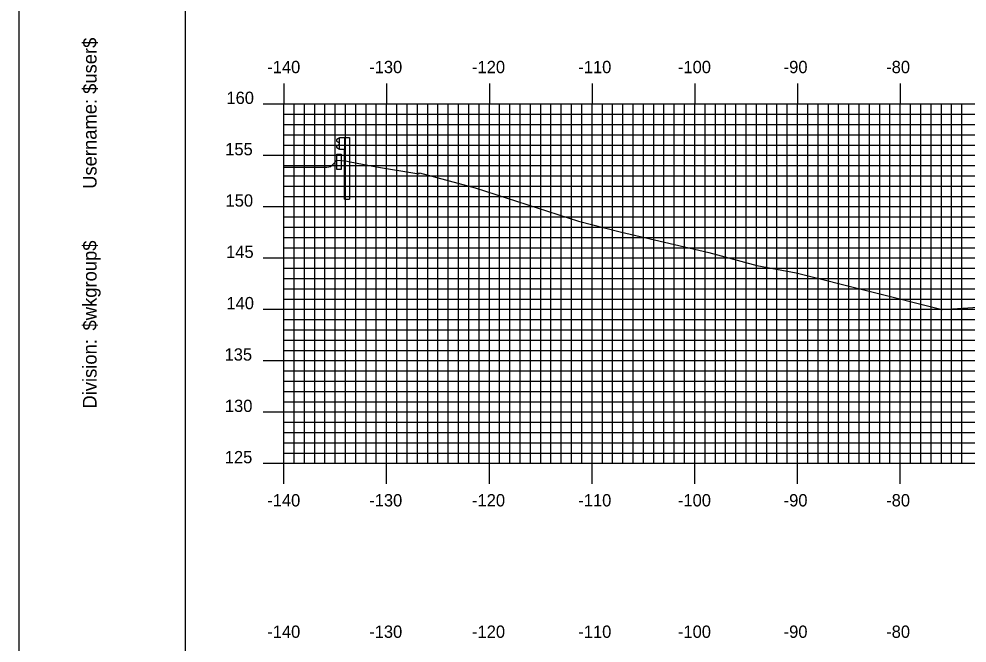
# Model space of a CAD drawing. Extents: x 850966 to 851310, y 364661 to 364881.
# Drawn here: x 850966.4 to 851058.7, y 364726.9 to 364787.7 of the extents above; entities that cross this region are included whole.
import ezdxf

# ---------------------------------------------------------------- set-up
doc = ezdxf.new("R2010")
doc.units = 0
for name, color, linetype in [('BORDER', 7, 'Continuous'), ('H_V ANNOTATION', 7, 'Continuous'), ('MAJOR', 7, 'Continuous'), ('MINOR', 7, 'Continuous'), ('PLOT BOUNDARY', 7, 'Continuous'), ('S_Curb_Type_1', 7, 'Continuous'), ('S_Guardrail_Beam', 7, 'Continuous'), ('S_Roadway_Centerline', 7, 'Continuous')]:
    doc.layers.add(name, color=color, linetype=linetype)

msp = doc.modelspace()

# ---------------------------------------------------------------- linework, layer by layer
at = {"layer": 'BORDER'}
msp.add_lwpolyline([(850982.616, 364667.37), (851302.616, 364667.37), (851302.616, 364877.37), (850982.616, 364877.37)], close=True, dxfattribs=at)
at = {"layer": 'MAJOR'}
for p, q in [((850992.216, 364781.374), (850992.216, 364779.37)), ((851002.216, 364781.374), (851002.216, 364779.37)), ((851012.216, 364781.374), (851012.216, 364779.37)), ((851022.216, 364781.374), (851022.216, 364779.37)), ((851032.216, 364781.374), (851032.216, 364779.37)), ((851042.216, 364781.374), (851042.216, 364779.37)), ((851052.216, 364781.374), (851052.216, 364779.37)), ((850990.212, 364779.37), (850992.216, 364779.37)), ((850992.216, 364779.37), (851272.216, 364779.37)), ((850992.216, 364744.37), (850992.216, 364779.37)), ((850992.216, 364744.37), (850992.216, 364779.37)), ((850992.216, 364779.37), (851272.216, 364779.37)), ((851002.216, 364744.37), (851002.216, 364779.37)), ((851012.216, 364744.37), (851012.216, 364779.37)), ((851022.216, 364744.37), (851022.216, 364779.37)), ((851032.216, 364744.37), (851032.216, 364779.37)), ((851042.216, 364744.37), (851042.216, 364779.37)), ((851052.216, 364744.37), (851052.216, 364779.37)), ((850990.212, 364774.37), (850992.216, 364774.37)), ((850992.216, 364774.37), (851272.216, 364774.37)), ((850990.212, 364769.37), (850992.216, 364769.37)), ((850992.216, 364769.37), (851272.216, 364769.37)), ((850990.212, 364764.37), (850992.216, 364764.37)), ((850992.216, 364764.37), (851272.216, 364764.37)), ((850990.212, 364759.37), (850992.216, 364759.37)), ((850992.216, 364759.37), (851272.216, 364759.37)), ((850990.212, 364754.37), (850992.216, 364754.37)), ((850992.216, 364754.37), (851272.216, 364754.37)), ((850990.212, 364749.37), (850992.216, 364749.37)), ((850992.216, 364749.37), (851272.216, 364749.37)), ((850990.212, 364744.37), (850992.216, 364744.37)), ((850992.216, 364744.37), (851272.216, 364744.37)), ((850992.216, 364744.37), (851272.216, 364744.37)), ((850992.216, 364742.366), (850992.216, 364744.37)), ((851002.216, 364742.366), (851002.216, 364744.37)), ((851012.216, 364742.366), (851012.216, 364744.37)), ((851022.216, 364742.366), (851022.216, 364744.37)), ((851032.216, 364742.366), (851032.216, 364744.37)), ((851042.216, 364742.366), (851042.216, 364744.37)), ((851052.216, 364742.366), (851052.216, 364744.37))]:
    msp.add_line(p, q, dxfattribs=at)
at = {"layer": 'MINOR'}
for p, q in [((850993.216, 364744.37), (850993.216, 364779.37)), ((850994.216, 364744.37), (850994.216, 364779.37)), ((850995.216, 364744.37), (850995.216, 364779.37)), ((850996.216, 364744.37), (850996.216, 364779.37)), ((850997.216, 364744.37), (850997.216, 364779.37)), ((850998.216, 364744.37), (850998.216, 364779.37)), ((850999.216, 364744.37), (850999.216, 364779.37)), ((851000.216, 364744.37), (851000.216, 364779.37)), ((851001.216, 364744.37), (851001.216, 364779.37)), ((851003.216, 364744.37), (851003.216, 364779.37)), ((851004.216, 364744.37), (851004.216, 364779.37)), ((851005.216, 364744.37), (851005.216, 364779.37)), ((851006.216, 364744.37), (851006.216, 364779.37)), ((851007.216, 364744.37), (851007.216, 364779.37)), ((851008.216, 364744.37), (851008.216, 364779.37)), ((851009.216, 364744.37), (851009.216, 364779.37)), ((851010.216, 364744.37), (851010.216, 364779.37)), ((851011.216, 364744.37), (851011.216, 364779.37)), ((851013.216, 364744.37), (851013.216, 364779.37)), ((851014.216, 364744.37), (851014.216, 364779.37)), ((851015.216, 364744.37), (851015.216, 364779.37)), ((851016.216, 364744.37), (851016.216, 364779.37)), ((851017.216, 364744.37), (851017.216, 364779.37)), ((851018.216, 364744.37), (851018.216, 364779.37)), ((851019.216, 364744.37), (851019.216, 364779.37)), ((851020.216, 364744.37), (851020.216, 364779.37)), ((851021.216, 364744.37), (851021.216, 364779.37)), ((851023.216, 364744.37), (851023.216, 364779.37)), ((851024.216, 364744.37), (851024.216, 364779.37)), ((851025.216, 364744.37), (851025.216, 364779.37)), ((851026.216, 364744.37), (851026.216, 364779.37)), ((851027.216, 364744.37), (851027.216, 364779.37)), ((851028.216, 364744.37), (851028.216, 364779.37)), ((851029.216, 364744.37), (851029.216, 364779.37)), ((851030.216, 364744.37), (851030.216, 364779.37)), ((851031.216, 364744.37), (851031.216, 364779.37)), ((851033.216, 364744.37), (851033.216, 364779.37)), ((851034.216, 364744.37), (851034.216, 364779.37)), ((851035.216, 364744.37), (851035.216, 364779.37)), ((851036.216, 364744.37), (851036.216, 364779.37)), ((851037.216, 364744.37), (851037.216, 364779.37)), ((851038.216, 364744.37), (851038.216, 364779.37)), ((851039.216, 364744.37), (851039.216, 364779.37)), ((851040.216, 364744.37), (851040.216, 364779.37)), ((851041.216, 364744.37), (851041.216, 364779.37)), ((851043.216, 364744.37), (851043.216, 364779.37)), ((851044.216, 364744.37), (851044.216, 364779.37)), ((851045.216, 364744.37), (851045.216, 364779.37)), ((851046.216, 364744.37), (851046.216, 364779.37)), ((851047.216, 364744.37), (851047.216, 364779.37)), ((851048.216, 364744.37), (851048.216, 364779.37)), ((851049.216, 364744.37), (851049.216, 364779.37)), ((851050.216, 364744.37), (851050.216, 364779.37)), ((851051.216, 364744.37), (851051.216, 364779.37)), ((851053.216, 364744.37), (851053.216, 364779.37)), ((851054.216, 364744.37), (851054.216, 364779.37)), ((851055.216, 364744.37), (851055.216, 364779.37)), ((851056.216, 364744.37), (851056.216, 364779.37)), ((851057.216, 364744.37), (851057.216, 364779.37)), ((851058.216, 364744.37), (851058.216, 364779.37)), ((850992.216, 364778.37), (851272.216, 364778.37)), ((850992.216, 364778.37), (850994.22, 364778.37)), ((850992.216, 364777.37), (851272.216, 364777.37)), ((850992.216, 364777.37), (850994.22, 364777.37)), ((850992.216, 364776.37), (851272.216, 364776.37)), ((850992.216, 364776.37), (850994.22, 364776.37)), ((850992.216, 364775.37), (851272.216, 364775.37)), ((850992.216, 364775.37), (850994.22, 364775.37)), ((850992.216, 364773.37), (851272.216, 364773.37)), ((850992.216, 364773.37), (850994.22, 364773.37)), ((850992.216, 364772.37), (851272.216, 364772.37)), ((850992.216, 364772.37), (850994.22, 364772.37)), ((850992.216, 364771.37), (851272.216, 364771.37)), ((850992.216, 364771.37), (850994.22, 364771.37)), ((850992.216, 364770.37), (851272.216, 364770.37)), ((850992.216, 364770.37), (850994.22, 364770.37)), ((850992.216, 364768.37), (851272.216, 364768.37)), ((850992.216, 364768.37), (850994.22, 364768.37)), ((850992.216, 364767.37), (851272.216, 364767.37)), ((850992.216, 364767.37), (850994.22, 364767.37)), ((850992.216, 364766.37), (851272.216, 364766.37)), ((850992.216, 364766.37), (850994.22, 364766.37)), ((850992.216, 364765.37), (851272.216, 364765.37)), ((850992.216, 364765.37), (850994.22, 364765.37)), ((850992.216, 364763.37), (851272.216, 364763.37)), ((850992.216, 364763.37), (850994.22, 364763.37)), ((850992.216, 364762.37), (851272.216, 364762.37)), ((850992.216, 364762.37), (850994.22, 364762.37)), ((850992.216, 364761.37), (851272.216, 364761.37)), ((850992.216, 364761.37), (850994.22, 364761.37)), ((850992.216, 364760.37), (851272.216, 364760.37)), ((850992.216, 364760.37), (850994.22, 364760.37)), ((850992.216, 364758.37), (851272.216, 364758.37)), ((850992.216, 364758.37), (850994.22, 364758.37)), ((850992.216, 364757.37), (851272.216, 364757.37)), ((850992.216, 364757.37), (850994.22, 364757.37)), ((850992.216, 364756.37), (851272.216, 364756.37)), ((850992.216, 364756.37), (850994.22, 364756.37)), ((850992.216, 364755.37), (851272.216, 364755.37)), ((850992.216, 364755.37), (850994.22, 364755.37)), ((850992.216, 364753.37), (851272.216, 364753.37)), ((850992.216, 364753.37), (850994.22, 364753.37)), ((850992.216, 364752.37), (851272.216, 364752.37)), ((850992.216, 364752.37), (850994.22, 364752.37)), ((850992.216, 364751.37), (851272.216, 364751.37)), ((850992.216, 364751.37), (850994.22, 364751.37)), ((850992.216, 364750.37), (851272.216, 364750.37)), ((850992.216, 364750.37), (850994.22, 364750.37)), ((850992.216, 364748.37), (851272.216, 364748.37)), ((850992.216, 364748.37), (850994.22, 364748.37)), ((850992.216, 364747.37), (851272.216, 364747.37)), ((850992.216, 364747.37), (850994.22, 364747.37)), ((850992.216, 364746.37), (851272.216, 364746.37)), ((850992.216, 364746.37), (850994.22, 364746.37)), ((850992.216, 364745.37), (851272.216, 364745.37)), ((850992.216, 364745.37), (850994.22, 364745.37))]:
    msp.add_line(p, q, dxfattribs=at)
at = {"layer": 'PLOT BOUNDARY'}
msp.add_lwpolyline([(850966.429, 364661.252), (851306.429, 364661.252), (851306.429, 364881.252), (850966.429, 364881.252)], close=True, dxfattribs=at)
at = {"layer": 'S_Curb_Type_1'}
msp.add_lwpolyline([(850997.367, 364774.492), (850997.783, 364774.492), (850997.783, 364772.992), (850997.367, 364772.992)], close=True, dxfattribs=at)
msp.add_lwpolyline([(850997.367, 364774.492), (850997.783, 364774.492), (850997.783, 364772.992), (850997.367, 364772.992)], close=True, dxfattribs=at)
at = {"layer": 'S_Guardrail_Beam'}
for p, q in [((850997.619, 364776.092), (850998.109, 364776.092)), ((850997.619, 364774.925), (850997.619, 364776.092)), ((850997.619, 364776.092), (850998.109, 364776.092)), ((850997.619, 364774.925), (850997.619, 364776.092)), ((850998.109, 364776.092), (850998.6, 364776.092)), ((850998.109, 364776.092), (850998.109, 364774.925)), ((850998.109, 364776.092), (850998.6, 364776.092)), ((850998.109, 364776.092), (850998.109, 364774.925)), ((850998.6, 364776.092), (850998.6, 364770.092)), ((850998.6, 364776.092), (850998.6, 364770.092)), ((850997.52, 364775.997), (850997.377, 364775.897)), ((850997.52, 364775.997), (850997.377, 364775.897)), ((850997.377, 364775.754), (850997.572, 364775.618)), ((850997.377, 364775.754), (850997.572, 364775.618)), ((850997.572, 364775.398), (850997.377, 364775.262)), ((850997.572, 364775.398), (850997.377, 364775.262)), ((850997.619, 364776.019), (850997.537, 364776.004)), ((850997.619, 364776.019), (850997.537, 364776.004)), ((850997.606, 364775.554), (850997.606, 364775.463)), ((850997.606, 364775.554), (850997.606, 364775.463)), ((850997.377, 364775.119), (850997.52, 364775.019)), ((850997.377, 364775.119), (850997.52, 364775.019)), ((850997.537, 364775.012), (850997.619, 364774.998)), ((850997.537, 364775.012), (850997.619, 364774.998)), ((850998.109, 364774.925), (850997.619, 364774.925)), ((850998.109, 364774.925), (850997.619, 364774.925)), ((850998.109, 364770.092), (850998.109, 364774.925)), ((850998.109, 364770.092), (850998.109, 364774.925)), ((850998.109, 364770.092), (850998.6, 364770.092)), ((850998.109, 364770.092), (850998.6, 364770.092))]:
    msp.add_line(p, q, dxfattribs=at)
for centre, major_axis, start_param, end_param in [((850997.427, 364775.826), (-0.0877, 0), 5.323254, 7.243116), ((850997.427, 364775.826), (-0.0877, 0), 5.323254, 7.243116), ((850997.427, 364775.191), (-0.0877, 0), 5.323254, 7.243116), ((850997.427, 364775.191), (-0.0877, 0), 5.323254, 7.243116), ((850997.544, 364775.963), (-0.0417, 0), 4.886922, 5.323254), ((850997.544, 364775.963), (-0.0417, 0), 4.886922, 5.323254), ((850997.527, 364775.554), (0.0789, 0), 0, 0.959931), ((850997.527, 364775.554), (0.0789, 0), 0, 0.959931), ((850997.527, 364775.463), (0.0789, 0), 5.323254, 6.283185), ((850997.527, 364775.463), (0.0789, 0), 5.323254, 6.283185), ((850997.544, 364775.053), (-0.0417, 0), 0.959931, 1.396263), ((850997.544, 364775.053), (-0.0417, 0), 0.959931, 1.396263)]:
    msp.add_ellipse(centre, major_axis=major_axis, ratio=0.995501, start_param=start_param, end_param=end_param, dxfattribs=at)
at = {"layer": 'S_Roadway_Centerline'}
msp.add_lwpolyline([(850992.216, 364773.228), (850996.402, 364773.219), (850996.774, 364773.269), (850997.039, 364773.54), (850997.367, 364773.908), (850998.22, 364773.832), (850998.685, 364773.724), (851001.23, 364773.249), (851005.364, 364772.569), (851005.43, 364772.663), (851010.852, 364771.204), (851020.906, 364767.957), (851024.959, 364766.921), (851033.566, 364764.91), (851038.257, 364763.645), (851042.074, 364762.929), (851056.289, 364759.338), (851070.769, 364760.283), (851072.231, 364760.455), (851072.973, 364760.743), (851075.083, 364761.652), (851091.309, 364768.334), (851098.604, 364770.618), (851100.03, 364771.035)], dxfattribs=at)

# ---------------------------------------------------------------- texts
at = {"layer": 'BORDER'}
for s, p in [('$user$', (850973.986, 364780.353)), ('Username:', (850973.986, 364771.106)), ('$wkgroup$', (850973.986, 364757.309)), ('Division:', (850973.986, 364749.702))]:
    msp.add_text(s, height=1.3392, rotation=90, dxfattribs=at).set_placement(p)
at = {"layer": 'H_V ANNOTATION'}
for s, p in [('-140', (850990.6, 364782.37)), ('-130', (851000.525, 364782.37)), ('-120', (851010.535, 364782.37)), ('-110', (851020.878, 364782.37)), ('-100', (851030.578, 364782.37)), ('-90', (851040.867, 364782.37)), ('-80', (851050.846, 364782.37)), ('160', (850986.626, 364779.37)), ('155', (850986.508, 364774.37)), ('150', (850986.54, 364769.37)), ('145', (850986.593, 364764.37)), ('140', (850986.626, 364759.37)), ('135', (850986.444, 364754.37)), ('130', (850986.476, 364749.37)), ('125', (850986.465, 364744.37)), ('-140', (850990.6, 364740.17)), ('-130', (851000.525, 364740.17)), ('-120', (851010.535, 364740.17)), ('-110', (851020.878, 364740.17)), ('-100', (851030.578, 364740.17)), ('-90', (851040.867, 364740.17)), ('-80', (851050.846, 364740.17)), ('-140', (850990.6, 364727.37)), ('-130', (851000.525, 364727.37)), ('-120', (851010.535, 364727.37)), ('-110', (851020.878, 364727.37)), ('-100', (851030.578, 364727.37)), ('-90', (851040.867, 364727.37)), ('-80', (851050.846, 364727.37))]:
    msp.add_text(s, height=1.2, dxfattribs=at).set_placement(p)
at = {"layer": 'MAJOR'}
msp.add_text('-', height=0.012, dxfattribs=at).set_placement((850992.207, 364744.37))

doc.saveas('drawing.dxf')
